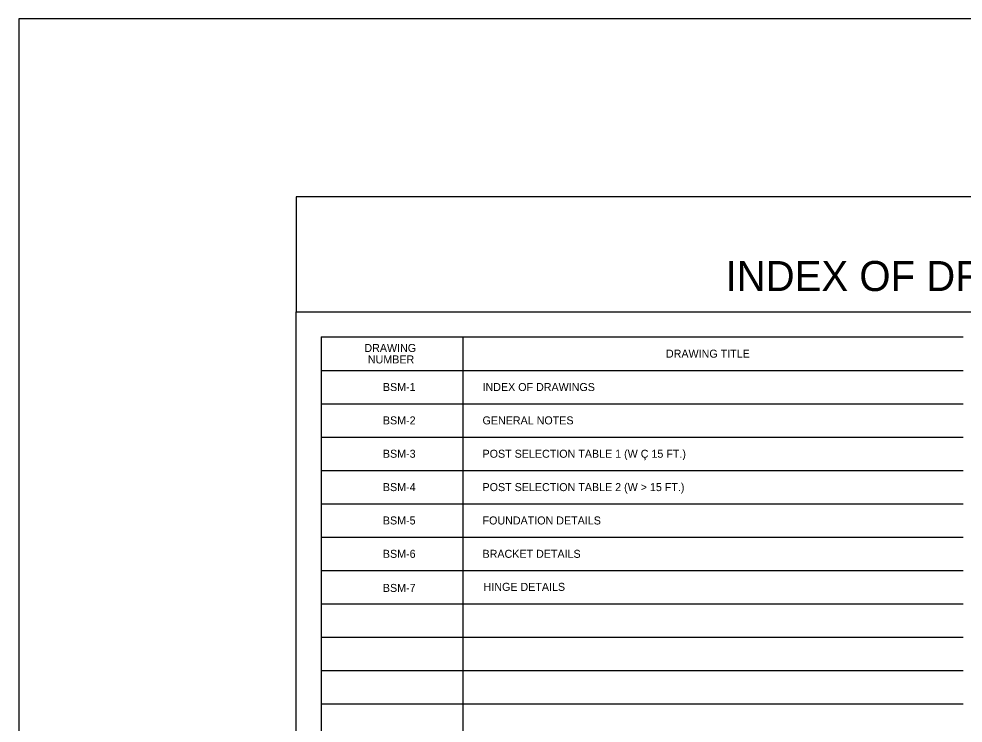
# Model space of a CAD drawing. Extents: x 0 to 31.8, y -0.5 to 20.8.
# Drawn here: x 0 to 14.16, y 10.19 to 20.75 of the extents above; entities that cross this region are included whole.
import ezdxf

# ---------------------------------------------------------------- set-up
doc = ezdxf.new("R2010")
doc.units = 0
for name, color, linetype in [('ct_Bdr_Txt_Titleblock', 7, 'Continuous'), ('CT_Border_Perimeter_Shape', 7, 'Continuous'), ('CT_TSH_Annotation_Locked', 7, 'Continuous'), ('CT_TSH_Line_Work_Major', 7, 'Continuous'), ('CT_TSH_Line_Work_Minor', 7, 'Continuous')]:
    doc.layers.add(name, color=color, linetype=linetype)

msp = doc.modelspace()

# ---------------------------------------------------------------- linework, layer by layer
at = {"layer": 'CT_Border_Perimeter_Shape'}
msp.add_lwpolyline([(0, 0), (31.75, 0), (31.75, 20.75), (0, 20.75)], close=True, dxfattribs=at)
at = {"layer": 'CT_TSH_Line_Work_Major'}
for p, q in [((4.156, 16.357), (24.156, 16.357)), ((4.156, 5.107), (4.156, 16.357))]:
    msp.add_line(p, q, dxfattribs=at)
msp.add_lwpolyline([(4.156, 16.357), (24.156, 16.357), (24.156, 18.084), (4.156, 18.084)], close=True, dxfattribs=at)
at = {"layer": 'CT_TSH_Line_Work_Minor'}
for p, q in [((4.531, 15.982), (4.531, 5.482)), ((4.531, 15.982), (14.156, 15.982)), ((6.656, 15.982), (6.656, 5.482)), ((4.531, 15.482), (14.156, 15.482)), ((4.531, 14.982), (14.156, 14.982)), ((4.531, 14.482), (14.156, 14.482)), ((4.531, 13.982), (14.156, 13.982)), ((4.531, 13.482), (14.156, 13.482)), ((4.531, 12.982), (14.156, 12.982)), ((4.531, 12.482), (14.156, 12.482)), ((4.531, 11.982), (14.156, 11.982)), ((4.531, 11.482), (14.156, 11.482)), ((4.531, 10.982), (14.156, 10.982)), ((4.531, 10.482), (14.156, 10.482))]:
    msp.add_line(p, q, dxfattribs=at)

# ---------------------------------------------------------------- texts
at = {"layer": 'ct_Bdr_Txt_Titleblock'}
for s, p in [('BSM-1', (5.457, 15.172)), ('INDEX OF DRAWINGS', (6.951, 15.172)), ('BSM-2', (5.457, 14.672)), ('GENERAL NOTES', (6.951, 14.672)), ('POST SELECTION TABLE 1 (W Ç 15 FT.)', (6.951, 14.172)), ('BSM-3', (5.457, 14.172)), ('BSM-4', (5.457, 13.672)), ('POST SELECTION TABLE 2 (W > 15 FT.)', (6.951, 13.672)), ('BSM-5', (5.457, 13.172)), ('FOUNDATION DETAILS', (6.951, 13.172)), ('BSM-6', (5.457, 12.672)), ('BRACKET DETAILS', (6.951, 12.672)), ('BSM-7', (5.457, 12.161)), ('HINGE DETAILS', (6.967, 12.177))]:
    msp.add_text(s, height=0.12, dxfattribs=at).set_placement(p)
at = {"layer": 'CT_TSH_Annotation_Locked'}
for s, height, p in [('INDEX OF DRAWINGS', 0.45, (10.594, 16.671)), ('DRAWING', 0.12, (5.18, 15.757)), ('DRAWING TITLE', 0.12, (9.701, 15.672)), ('NUMBER', 0.12, (5.232, 15.586))]:
    msp.add_text(s, height=height, dxfattribs=at).set_placement(p)

doc.saveas('drawing.dxf')
